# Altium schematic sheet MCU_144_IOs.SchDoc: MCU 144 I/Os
size A4; Date: Not used; ApprovedBy: Not used; CheckedBy: Not used; Author: Not used; CompanyName: STMicroelectronics; DrawnBy: Not used; Engineer: Not used; Organization: Not used; Address1: Not used; Address2: Not used; Address3: Not used; Address4: Not used; DocumentNumber: 3; Revision: Not used; SheetNumber: 3; SheetTotal: 9
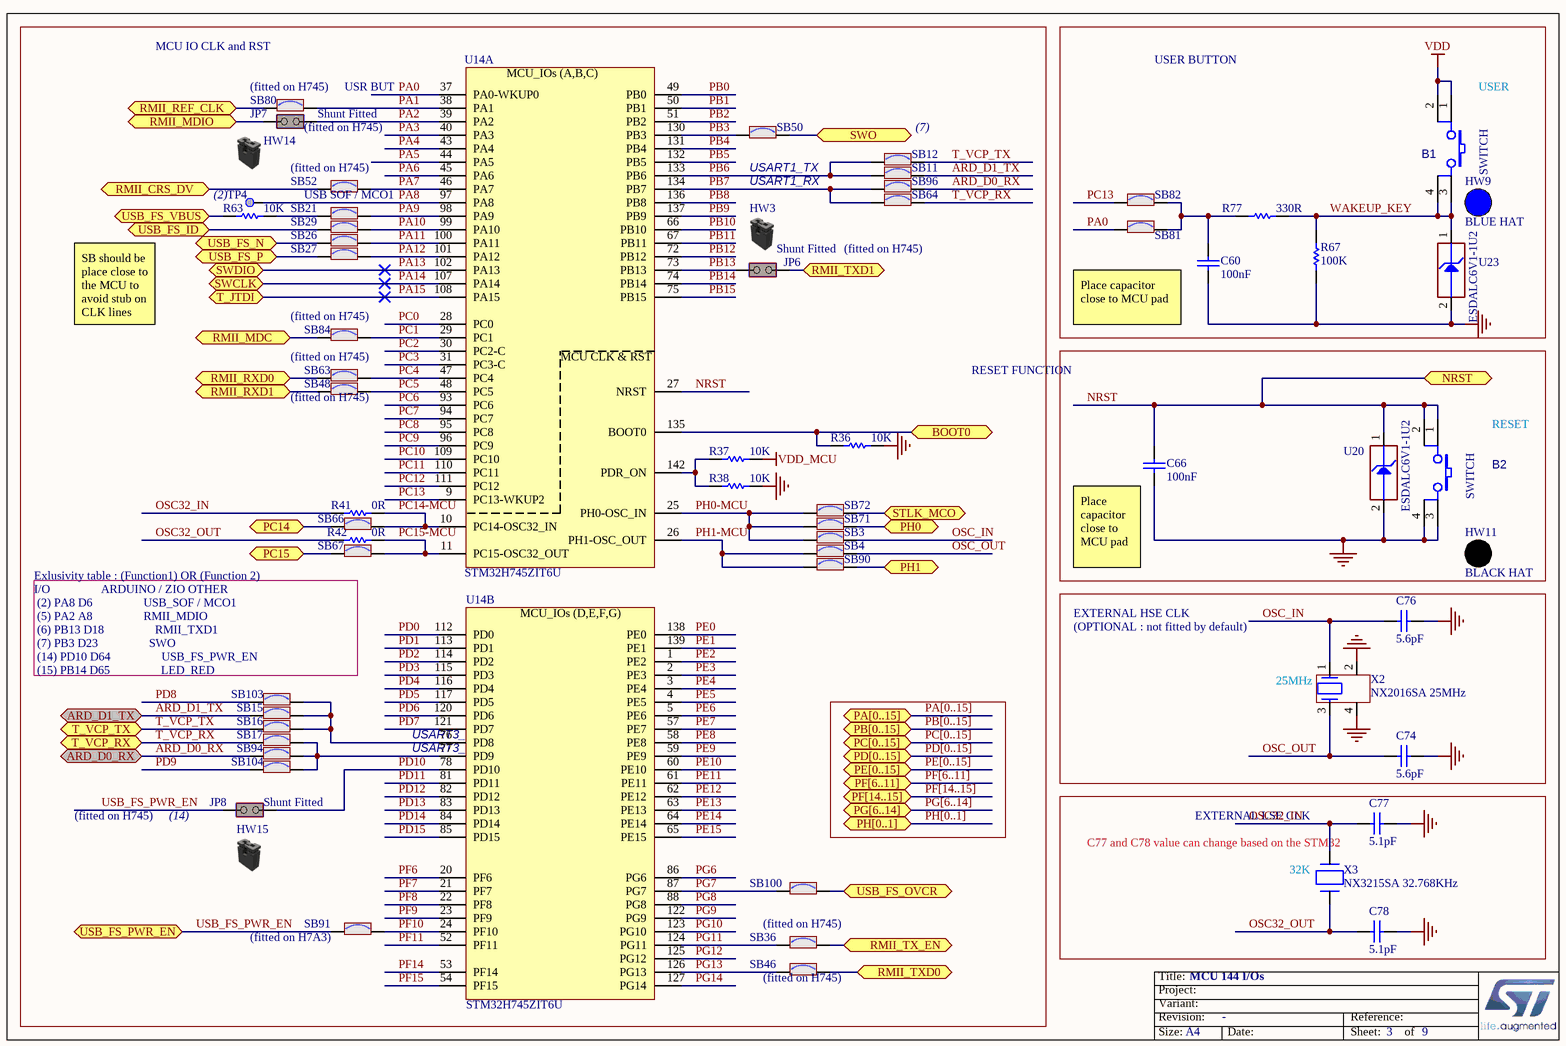
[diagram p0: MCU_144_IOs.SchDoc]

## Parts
B1  value SWITCH  [SWI_WEALTHMETAL_TD-0341_4P_BLUE]  (hidden comment: SW-PUSH-CMS)
B2  value SWITCH  [SWI_WEALTHMETAL_TD-0341_4P_BLACK]  (hidden comment: SW-PUSH-CMS)
C60  value 100nF  [C0603]  (hidden comment: Capacitor)
C66  value 100nF  [C0603]  (hidden comment: Capacitor)
C74  value 5.6pF  [C0402]  (hidden comment: Capacitor)
C76  value 5.6pF  [C0402]  (hidden comment: Capacitor)
C77  value 5.1pF  [C0603]  (hidden comment: Capacitor)
C78  value 5.1pF  [C0603]  (hidden comment: Capacitor)
HW3  Shunt Black 2.54mm  (value not drawn)  (mechanical)
HW9  value BLUE HAT  (hidden comment: BUTTON_HAT_BLUE)  (mechanical)
HW11  value BLACK HAT  (hidden comment: BUTTON_HAT_BLACK)  (mechanical)
HW14  Shunt Black 2.54mm  (value not drawn)  (mechanical)
HW15  Shunt Black 2.54mm  (value not drawn)  (mechanical)
JP6  value Shunt Fitted  [CON_SAMTEC_TSW-102-07-G-S]  (hidden comment: Jumper_Header 2x1 Fitted)
JP7  value Shunt Fitted  [CON_SAMTEC_TSW-102-07-G-S]  (hidden comment: Jumper_Header 2x1 Fitted)
JP8  value Shunt Fitted  [CON_SAMTEC_TSW-102-07-G-S]  (hidden comment: Jumper_Header 2x1 Fitted)
R36  value 10K  [R0603]  (hidden comment: Resistor)
R37  value 10K  [R0603]  (hidden comment: Resistor)
R38  value 10K  [R0603]  (hidden comment: Resistor)
R41  value 0R  [R0603]  (hidden comment: Resistor)
R42  value 0R  [R0603]  (hidden comment: Resistor)
R63  value 10K  [R0402]  (hidden comment: Resistor)
R67  value 100K  [R0603]  (hidden comment: Resistor)
R77  value 330R  [R0603]  (hidden comment: Resistor)
SB3  SB_ON  [SOLDER-BRIDGE_R0603-0R]  (value not drawn)
SB4  SB_ON  [SOLDER-BRIDGE_R0603-0R]  (value not drawn)
SB11  SB_ON  [SOLDER-BRIDGE_R0603-0R]  (value not drawn)
SB12  SB_ON  [SOLDER-BRIDGE_R0603-0R]  (value not drawn)
SB15  SB_ON  [SOLDER-BRIDGE_R0603-0R]  (value not drawn)
SB16  SB_ON  [SOLDER-BRIDGE_R0603-0R]  (value not drawn)
SB17  SB_ON  [SOLDER-BRIDGE_R0603-0R]  (value not drawn)
SB21  SB_ON  [SOLDER-BRIDGE_R0603-0R]  (value not drawn)
SB26  SB_ON  [SOLDER-BRIDGE_R0603-0R]  (value not drawn)
SB27  SB_ON  [SOLDER-BRIDGE_R0603-0R]  (value not drawn)
SB29  SB_ON  [SOLDER-BRIDGE_R0603-0R]  (value not drawn)
SB36  SB_ON  [SOLDER-BRIDGE_R0603-0R]  (value not drawn)
SB46  SB_ON  [SOLDER-BRIDGE_R0603-0R]  (value not drawn)
SB48  SB_ON  [SOLDER-BRIDGE_R0603-0R]  (value not drawn)
SB50  SB_ON  [SOLDER-BRIDGE_R0603-0R]  (value not drawn)
SB52  SB_ON  [SOLDER-BRIDGE_R0603-0R]  (value not drawn)
SB63  SB_ON  [SOLDER-BRIDGE_R0603-0R]  (value not drawn)
SB64  SB_ON  [SOLDER-BRIDGE_R0603-0R]  (value not drawn)
SB66  SB_ON  [SOLDER-BRIDGE_R0603-0R]  (value not drawn)
SB67  SB_ON  [SOLDER-BRIDGE_R0603-0R]  (value not drawn)
SB71  SB_ON  [SOLDER-BRIDGE_R0603-0R]  (value not drawn)
SB72  SB_ON  [SOLDER-BRIDGE_R0603-0R]  (value not drawn)
SB80  SB_ON  [SOLDER-BRIDGE_R0603-0R]  (value not drawn)
SB81  SB_ON  [SOLDER-BRIDGE_R0603-0R]  (value not drawn)
SB82  SB_ON  [SOLDER-BRIDGE_R0603-0R]  (value not drawn)
SB84  SB_ON  [SOLDER-BRIDGE_R0603-0R]  (value not drawn)
SB90  SB_ON  [SOLDER-BRIDGE_R0603-0R]  (value not drawn)
SB91  SB_ON  [SOLDER-BRIDGE_R0603-0R]  (value not drawn)
SB94  SB_ON  [SOLDER-BRIDGE_R0603-0R]  (value not drawn)
SB96  SB_ON  [SOLDER-BRIDGE_R0603-0R]  (value not drawn)
SB100  SB_ON  [SOLDER-BRIDGE_R0603-0R]  (value not drawn)
SB103  SB_ON  [SOLDER-BRIDGE_R0603-0R]  (value not drawn)
SB104  SB_ON  [SOLDER-BRIDGE_R0603-0R]  (value not drawn)
TP4  Test Point  [TP_SMD_1MM]  (value not drawn)  (no BOM)
U14  value STM32H745ZIT6U  [ICC_LQFP144_20X20_P050_SOCKET_YAMAICHI_IC149-144-145-B5_NM]  (hidden comment: STM32H7_LQFP144_SMPS)  (parts A,B of 3)
U20  value ESDALC6V1-1U2  [ESD_ST0201]  (hidden comment: ESD-TRANSIL)
U23  value ESDALC6V1-1U2  [ESD_ST0201]  (hidden comment: ESD-TRANSIL)
X2  value NX2016SA 25MHz  [CRY_NX2016SA_4P]  (hidden comment: XTAL_4_PINS)
X3  value NX3215SA 32.768KHz  [CRY_NX3215SA_2P]  (hidden comment: XTAL_2_PINS)

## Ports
ARD_D0_RX (bidir), ARD_D1_TX (bidir), BOOT0 (bidir), NRST (bidir), PA[0..15] (bidir), PB[0..15] (bidir), PC14 (bidir), PC15 (bidir), PC[0..15] (bidir), PD[0..15] (bidir), PE[0..15] (bidir), PF[6..11] (bidir), PF[14..15] (bidir), PG[6..14] (bidir), PH0 (bidir), PH1 (bidir), PH[0..1] (bidir), RMII_CRS_DV (bidir), RMII_MDC (bidir), RMII_MDIO (bidir), RMII_REF_CLK (bidir), RMII_RXD0 (bidir), RMII_RXD1 (bidir), RMII_TX_EN (bidir), RMII_TXD0 (bidir), RMII_TXD1 (bidir), STLK_MCO (bidir), SWCLK (bidir), SWDIO (bidir), SWO (bidir), T_JTDI (bidir), T_VCP_RX (bidir), T_VCP_TX (bidir), USB_FS_ID (bidir), USB_FS_N (bidir), USB_FS_OVCR, USB_FS_P (bidir), USB_FS_PWR_EN, USB_FS_VBUS (bidir)

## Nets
GND: B2.3 B2.4 C60.1 C66.1 C74.2 C76.2 C77.2 C78.2 R36.2 R38.2 R67.1 U20.2(GND) U23.2(GND) X2.2 X2.4
VDD: B1.1 B1.2
VDD_MCU: R37.2
ARD_D0_RX: SB94.2 SB96.1 ; port ARD_D0_RX
ARD_D1_TX: SB11.1 SB15.2 ; port ARD_D1_TX
BOOT0: R36.1 U14.135(BOOT0) ; port BOOT0
NRST: B2.1 B2.2 C66.2 U14.27(NRST) U20.1(IO1) ; port NRST
OSC32_IN: C77.1 R41.2 X3.2(X2)
OSC32_OUT: C78.1 R42.1 X3.1(X1)
OSC_IN: C76.1 SB3.2 X2.1
OSC_OUT: C74.1 SB4.2 X2.3
PA0: SB81.2 U14.37(PA0-WKUP0)
PA1: SB80.1 U14.38(PA1)
PA2: JP7.2(NO) U14.39(PA2)
PA3: U14.40(PA3)
PA4: U14.43(PA4)
PA5: U14.44(PA5)
PA6: U14.45(PA6)
PA7: SB52.1 U14.46(PA7)
PA8: TP4.1 U14.97(PA8)
PA9: SB21.1 U14.98(PA9)
PA10: SB29.1 U14.99(PA10)
PA11: SB26.1 U14.100(PA11)
PA12: SB27.1 U14.101(PA12)
PA13: U14.102(PA13) ; port SWDIO
PA14: U14.107(PA14) ; port SWCLK
PA15: U14.108(PA15) ; port T_JTDI
PB0: U14.49(PB0)
PB1: U14.50(PB1)
PB2: U14.51(PB2)
PB3: SB50.2 U14.130(PB3)
PB4: U14.131(PB4)
PB5: U14.132(PB5)
PB6: SB11.2 SB12.2 U14.133(PB6)
PB7: SB64.2 SB96.2 U14.134(PB7)
PB8: U14.136(PB8)
PB9: U14.137(PB9)
PB10: U14.66(PB10)
PB11: U14.67(PB11)
PB12: U14.72(PB12)
PB13: JP6.1(COMMON) U14.73(PB13)
PB14: U14.74(PB14)
PB15: U14.75(PB15)
PC0: U14.28(PC0)
PC1: SB84.2 U14.29(PC1)
PC2: U14.30(PC2-C)
PC3: U14.31(PC3-C)
PC4: SB63.2 U14.47(PC4)
PC5: SB48.2 U14.48(PC5)
PC6: U14.93(PC6)
PC7: U14.94(PC7)
PC8: U14.95(PC8)
PC9: U14.96(PC9)
PC10: U14.109(PC10)
PC11: U14.110(PC11)
PC12: U14.111(PC12)
PC13: SB82.2 U14.9(PC13-WKUP2)
PC14: SB66.1 ; port PC14
PC14-MCU: R41.1 SB66.2 U14.10(PC14-OSC32_IN)
PC15: SB67.1 ; port PC15
PC15-MCU: R42.2 SB67.2 U14.11(PC15-OSC32_OUT)
PD0: U14.112(PD0)
PD1: U14.113(PD1)
PD2: U14.114(PD2)
PD3: U14.115(PD3)
PD4: U14.116(PD4)
PD5: U14.117(PD5)
PD6: U14.120(PD6)
PD7: U14.121(PD7)
PD8: SB103.1
PD9: SB104.1
PD10: JP8.2(NO) U14.78(PD10)
PD11: U14.81(PD11)
PD12: U14.82(PD12)
PD13: U14.83(PD13)
PD14: U14.84(PD14)
PD15: U14.85(PD15)
PE0: U14.138(PE0)
PE1: U14.139(PE1)
PE2: U14.1(PE2)
PE3: U14.2(PE3)
PE4: U14.3(PE4)
PE5: U14.4(PE5)
PE6: U14.5(PE6)
PE7: U14.57(PE7)
PE8: U14.58(PE8)
PE9: U14.59(PE9)
PE10: U14.60(PE10)
PE11: U14.61(PE11)
PE12: U14.62(PE12)
PE13: U14.63(PE13)
PE14: U14.64(PE14)
PE15: U14.65(PE15)
PF6: U14.20(PF6)
PF7: U14.21(PF7)
PF8: U14.22(PF8)
PF9: U14.23(PF9)
PF10: SB91.1 U14.24(PF10)
PF11: U14.52(PF11)
PF14: U14.53(PF14)
PF15: U14.54(PF15)
PG6: U14.86(PG6)
PG7: SB100.2 U14.87(PG7)
PG8: U14.88(PG8)
PG9: U14.122(PG9)
PG10: U14.123(PG10)
PG11: SB36.2 U14.124(PG11)
PG12: U14.125(PG12)
PG13: SB46.2 U14.126(PG13)
PG14: U14.127(PG14)
PH0: SB71.2 ; port PH0
PH0-MCU: SB3.1 SB71.1 SB72.1 U14.25(PH0-OSC_IN)
PH1: SB90.2 ; port PH1
PH1-MCU: SB4.1 SB90.1 U14.26(PH1-OSC_OUT)
RMII_CRS_DV: SB52.2 ; port RMII_CRS_DV
RMII_MDC: SB84.1 ; port RMII_MDC
RMII_MDIO: JP7.1(COMMON) ; port RMII_MDIO
RMII_REF_CLK: SB80.2 ; port RMII_REF_CLK
RMII_RXD0: SB63.1 ; port RMII_RXD0
RMII_RXD1: SB48.1 ; port RMII_RXD1
RMII_TX_EN: SB36.1 ; port RMII_TX_EN
RMII_TXD0: SB46.1 ; port RMII_TXD0
RMII_TXD1: JP6.2(NO) ; port RMII_TXD1
STLK_MCO: SB72.2 ; port STLK_MCO
SWO: SB50.1 ; port SWO
T_VCP_RX: SB17.2 SB64.1 ; port T_VCP_RX
T_VCP_TX: SB12.1 SB16.2 ; port T_VCP_TX
USB_FS_ID: SB29.2 ; port USB_FS_ID
USB_FS_N: SB26.2 ; port USB_FS_N
USB_FS_OVCR: SB100.1 ; port USB_FS_OVCR
USB_FS_P: SB27.2 ; port USB_FS_P
USB_FS_PWR_EN: JP8.1(COMMON) SB91.2 ; port USB_FS_PWR_EN
USB_FS_VBUS: R63.1 ; port USB_FS_VBUS
WAKEUP_KEY: B1.3 B1.4 R67.2 R77.2 U23.1(IO1)
NetC60_2: C60.2 R77.1 SB81.1 SB82.1
NetR37_1: R37.1 R38.1 U14.142(PDR_ON)
NetR63_2: R63.2 SB21.2
NetSB15_1: SB15.1 SB16.1 SB103.2 U14.76(PD8)
NetSB17_1: SB17.1 SB94.1 SB104.2 U14.77(PD9)

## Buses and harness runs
bus PA[0..15] = port PA[0..15]
bus PB[0..15] = port PB[0..15]
bus PC[0..15] = port PC[0..15]
bus PD[0..15] = port PD[0..15]
bus PE[0..15] = port PE[0..15]
bus PF[6..11] = port PF[6..11]
bus PF[14..15] = port PF[14..15]
bus PG[6..14] = port PG[6..14]
bus PH[0..1] = port PH[0..1]

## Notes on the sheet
- MCU IO CLK and RST
- (near SB80) (fitted on H745)
- USR BUT
- USER BUTTON
- (near B1) USER
- (near SB52) (fitted on H745)
- (fitted on H745)
- USART1_TX
- USART1_RX
- (7)
- (2)
- (near SB52) USB SOF / MCO1
- SB should be place close to the MCU to avoid stub on CLK lines
- (near SB84) (fitted on H745)
- Place capacitor close to MCU pad
- RESET FUNCTION
- (near SB48) (fitted on H745)
- RESET
- Exlusivity table : (Function1) OR (Function 2)
- (near C66) Place capacitor close to MCU pad
- EXTERNAL HSE CLK
- (OPTIONAL : not fitted by default)
- I/O	                ARDUINO / ZIO	OTHER
  (2)	PA8	D6	                USB_SOF / MCO1
  (5)	PA2	A8	                RMII_MDIO
  (6)	PB13	D18	                RMII_TXD1
  (7)	PB3	D23	                SWO
  (14)	PD10	D64	                USB_FS_PWR_EN
  (15)	PB14	D65	                LED_RED
- (near X2) 25MHz
- USART3_TX
- USART3_RX
- (14)
- C77 and C78 value can change based on the STM32
- EXTERNAL LSE CLK
- (near SB36) (fitted on H745)
- (near X3) 32K
- (near SB91) (fitted on H7A3)
- (near SB46) (fitted on H745)

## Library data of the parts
B1 = MCD-00002: Non-Open Push-Button 0.1A 24V; Manufacturer_Part_Number: TD-0341; Manufacturer: WEALTHMETAL; Part_Type: Misc; Provided_By: SUBCO
B2 = MCD-00001: Non-Open Push-Button 0.1A 24V BLACK; Manufacturer_Part_Number: TD-0341; Manufacturer: WEALTHMETAL; Part_Type: Misc; Provided_By: SUBCO
C60 C66 = MCD-00237: Capacitor, MLCC, 100nF, 6V3, X5R, 10%, 0603, T=0,8mm; Manufacturer_Part_Number: CC0603KRX5R5BB104; Manufacturer: YAGEO; Provided_By: SUBCO; ECCN_US: EAR99; ECCN_EU: NEC
C74 C76 = MCD-01374: Capacitor, MLCC, 5.6pF, 50V, NPO, 5%, 0402, T=0,5mm; Manufacturer_Part_Number: CC0402BRNPO9BN5R6; Manufacturer: YAGEO; Provided_By: SUBCO
C77 C78 = MCD-01367: Capacitor,5.1pF,0.25pF,50V,NPO,0603; Manufacturer_Part_Number: CC0603CRNPO9BN5R1; Manufacturer: YAGEO; Provided_By: SUBCO
HW3 HW14 HW15 = MCD-00043: SHUNT 2.54mm BLACK; Manufacturer_Part_Number: SNT-100-BK-G; Manufacturer: SAMTEC; Part_Type: Mechanical; Alternate_Manufacturer_Part_Number: 316102S111A; Alternate_Manufacturer: JIUBABA; Provided_By: SUBCO
HW9 = MCD-00634: Blue Hat for switch TD0341X-G01-BLU; Part_Type: Mechanical; Manufacturer_Part_Number: 988.16.09.3.00002_SH-517; Manufacturer: JIUBABA; Provided_By: SUBCO
HW11 = MCD-00635: Black Hat for switch TD0341X-G01-BLA; Part_Type: Mechanical; Manufacturer_Part_Number: 988.16.09.3.00003_SH-517; Manufacturer: JIUBABA; Provided_By: SUBCO
JP6-JP8 = MCD-00683: Header, 2x1, 2,54mm, VR, TH, Height 5.84mm/2.54mm - Shunt Fitted by default; Part_Type: Connector; Manufacturer_Part_Number: TSW-102-07-x-S; Manufacturer: SAMTEC; Alternate_Manufacturer_Part_Number: 313102S111116; Alternate_Manufacturer: LIANYI; Provided_By: SUBCO
R36-R38 = MCD-00220: Resistor,10K,0603,1%,1/10W; Manufacturer_Part_Number: RC0603FR-0710KL; Manufacturer: YAGEO; Provided_By: SUBCO; ECCN_US: EAR99; ECCN_EU: NEC
R41 R42 = MCD-00056: Resistor,0R,0603,5%,1/10W; Manufacturer_Part_Number: RC0603JR-070RL; Manufacturer: YAGEO; Provided_By: SUBCO; ECCN_US: EAR99; ECCN_EU: NEC
R63 = MCD-00053: Resistor,10K,0402,1%,1/16W; Manufacturer_Part_Number: RC0402FR-0710KL; Manufacturer: YAGEO; Provided_By: SUBCO; ECCN_US: EAR99; ECCN_EU: NEC
R67 = MCD-00223: Resistor,100K,0603,1%,1/10W; Manufacturer_Part_Number: RC0603FR-07100KL; Manufacturer: YAGEO; Provided_By: SUBCO; ECCN_US: EAR99; ECCN_EU: NEC
R77 = MCD-00197: Resistor,330R,0603,1%,1/10W; Manufacturer_Part_Number: RC0603FR-07330RL; Manufacturer: YAGEO; BMS_Part_Number: 9129729; Provided_By: SUBCO; ECCN_US: EAR99; ECCN_EU: NEC
SB3 SB4 SB11 SB12 SB15-SB17 SB21 SB26 SB27 SB29 SB36 SB46 SB48 SB50 SB52 SB63 SB64 SB66 SB67 SB71 SB72 SB80-SB82 SB84 SB90 SB91 SB94 SB96 SB100 SB103 SB104 = MCD-00071: Solder Bridge ON; Part_Type: Mechanical; Manufacturer_Part_Number: RC0603JR-070RL; Manufacturer: YAGEO; Provided_By: SUBCO
TP4 = MCD-00074: Test Point 1mm; Part_Type: Mechanical
U14 = MCD-01401: STM32H745ZIT6U, LQFP144 package, 20x20, with socket footprint; Part_Type: IC; Manufacturer: STMICROELECTRONICS; BMS_Part_Number: 9175297 (cut 2.0); ECCN_US: 3A991A2; ECCN_EU: NEC; Provided_By: SUBCO with ST control
U20 U23 = MCD-00170: ESD protection 6V1; Part_Type: Diode; Manufacturer: STMICROELECTRONICS; BMS_Part_Number: 9151132; Provided_By: SUBCO with ST control; ECCN_US: EAR99; ECCN_EU: NEC
X2 = MCD-01364: Crystal 25MHz, 6pF, +-20ppm, 80ohms max, SMD; Part_Type: Crystal_Osc; Manufacturer_Part_Number: NX2016SA 25MHz EXS00A-CS11321; Manufacturer: NDK; BMS_Part_Number: 9157044; Provided_By: SUBCO; ECCN_US: EAR99; ECCN_EU: NEC
X3 = MCD-00091: Crystal 32.768kHz, 6pF, +-20ppm, 50Kohms max, SMD; Manufacturer_Part_Number: NX3215SA 32.768KHz EXS00A-MU00525; Manufacturer: NDK; Part_Type: Crystal_Osc; BMS_Part_Number: 9157034; Provided_By: SUBCO; ECCN_US: EAR99; ECCN_EU: NEC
